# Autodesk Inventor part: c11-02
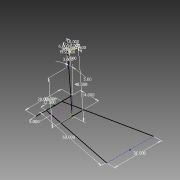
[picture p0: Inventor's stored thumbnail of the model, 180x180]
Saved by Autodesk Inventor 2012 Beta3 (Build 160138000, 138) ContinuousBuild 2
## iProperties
Created: 2010-12
Part Number: c11-02
Material: Default
Document SubType Name: Modeling
Designer: Beta-8540w
Density: 1 g/cm^3
Author: Beta-8540w
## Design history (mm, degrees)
sketch "Sketch1"
  geometry: L1 (355.6, 0)-(-355.6, 0); L2 (152.4, 0)-(457.2, 1493.209); L3 (-152.4, 0)-(-457.2, 1493.209); L4 (224.987, 355.6)-(-224.987, 355.6); L5 (457.2, 1493.209)-(-457.2, 1493.209); L6 (-178.324, 127)-(178.324, 127); 4 further points
  constraints: 12 end point, 6 point on line, 3 midpoint, 3 parallel, 2 vertical alignment, 1 coincident, 1 equal length, 1 horizontal
  dimensions: "d0" = 711.2 distance of L1.start L1.end; "d1" = 1524 distance of L2.start L2.end; "d2" = 304.8 distance of L3.start L2.start; "d3" = 355.6 distance between parallel lines of L1 L4; "d4" = 914.4 distance of L2.end L3.end; "d8" = 127 distance between parallel lines of L6 L1
sketch "Sketch2"
  geometry: L1 (355.6, 0)-(355.6, 346.923); L2 (355.6, 0)-(249.34, 1214.561); L3 (249.34, 1214.561)-(502.373, 1236.698); L4 (303.898, 1028.106)-(300.387, 1068.232); L5 (306.233, 1086.772)-(385.066, 1180.722); L6 (402.31, 1189.698)-(442.435, 1193.209); A1 r 25.4 centre (325.691, 1070.446) between (306.233, 1086.772) and (300.387, 1068.232); A2 r 25.4 centre (404.523, 1164.395) between (402.31, 1189.698) and (385.066, 1180.722); 3 further points
  constraints: 12 end point, 4 point on circle, 4 point on line, 4 tangent, 2 centre point, 2 parallel, 1 equal radius, 1 perpendicular, 1 vertical
  dimensions: "d5" = 1219.2 distance of L1.start L2.end; "d6" = 5 deg angle of L2 L1; "d11" = 254 distance of L2.end L3.end; "d12" = 50.8 distance of L4.start point (299.47, 1078.713) (= d13); "d13" = 50.8 distance of point (391.829, 1188.781) L6.end; "d14" = 25.4 radius of A1; "d15" = 45 deg angle of L5 L4; "d16" = 152.4 distance from line of L6 L4.start; "d17" = 38.1 distance between parallel lines of L3 L6; "d18" = 38.1 distance between parallel lines of L2 L4
workplane "Work Plane1"
sketch "Sketch3"
  geometry: L1 (224.987, 0)-(224.987, 1219.2) reference; L2 (186.887, 812.8)-(263.087, 812.8); 2 further points
  constraints: 2 end point, 1 midpoint, 1 perpendicular, 1 point on line
  dimensions: "d9" = 76.2 distance of L2.start L2.end; "d10" = 812.8 distance from line of L1.start L2
other parameters: "d16" = 152.4
